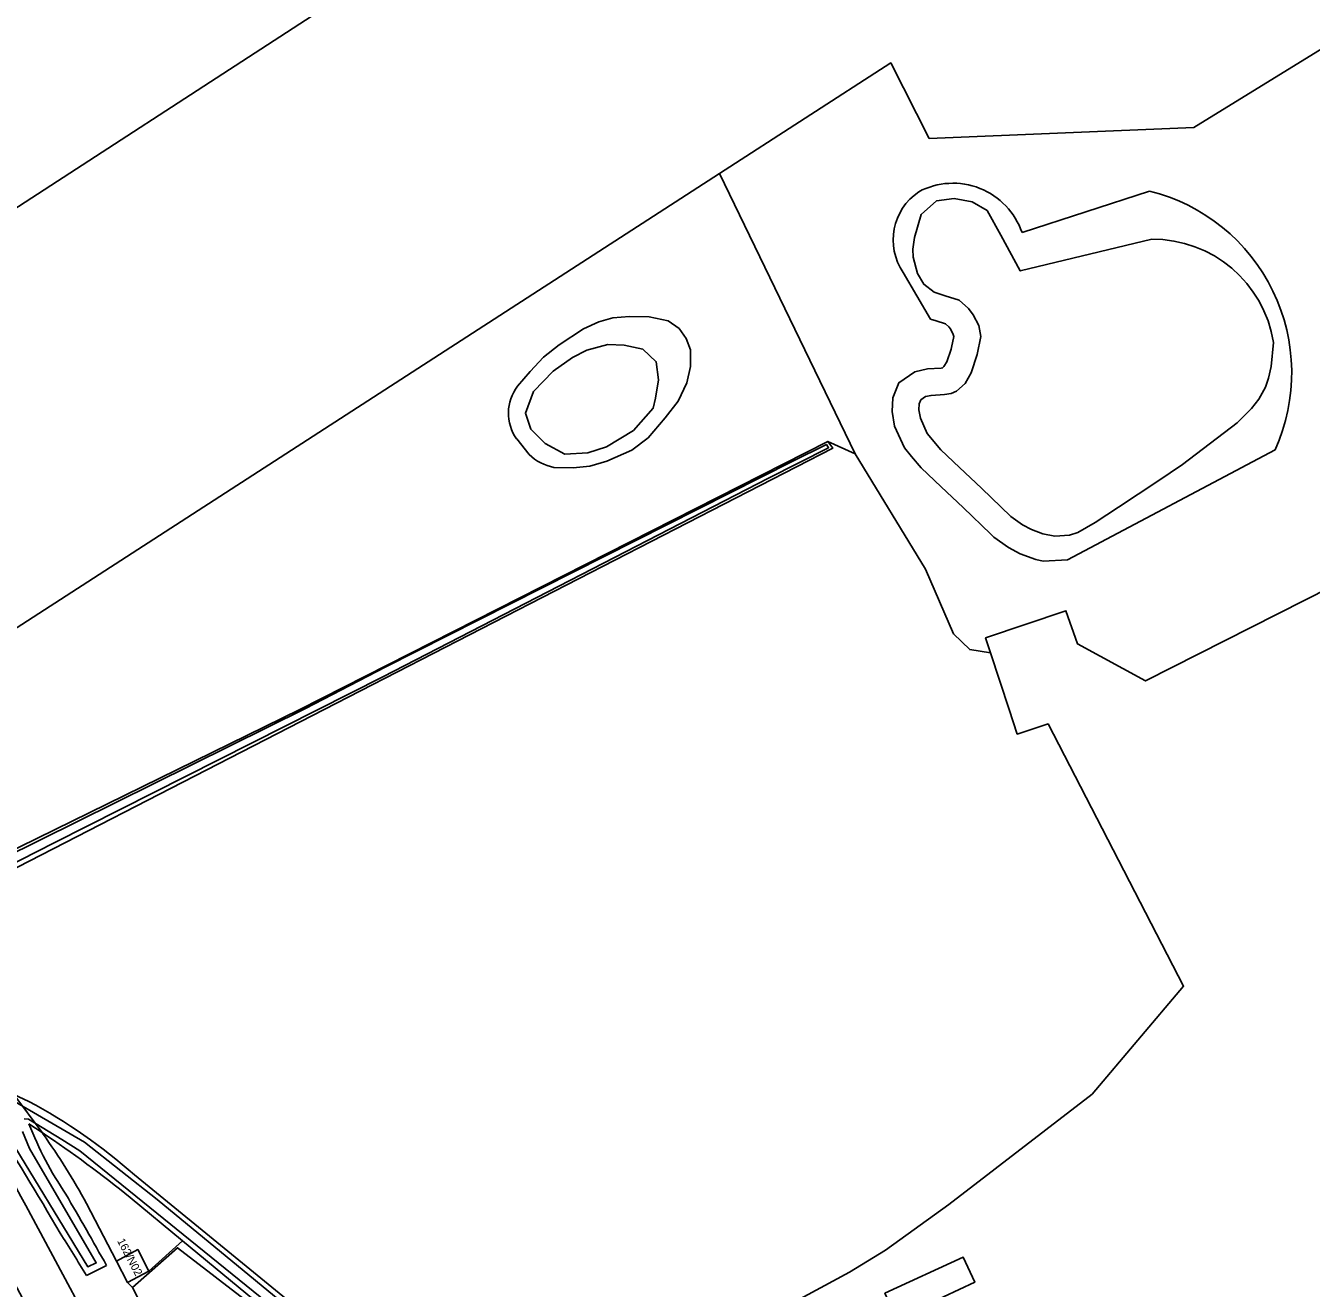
# Model space of a CAD drawing. Extents: x 156061 to 157804, y 383437 to 385640.
# Drawn here: x 157555.9 to 157716.6, y 383927.6 to 384085.5 of the extents above; entities that cross this region are included whole.
import ezdxf

# ---------------------------------------------------------------- set-up
doc = ezdxf.new("R2010")
doc.units = 0
for name, color, linetype in [('IMGEO_Bouwland', 7, 'Continuous'), ('IMGEO_Grasland_overig', 7, 'Continuous'), ('IMGEO_Groenvoorziening', 7, 'Continuous'), ('IMGEO_Hek', 7, 'Continuous'), ('IMGEO_Meer_plas_ven_vijver', 7, 'Continuous'), ('IMGEO_Oever', 7, 'Continuous'), ('IMGEO_Pand', 7, 'Continuous'), ('IMGEO_Pand_nummerreeks', 7, 'Continuous'), ('IMGEO_Rijbaan_lokaal_gesloten', 7, 'Continuous'), ('IMGEO_Waterloop', 7, 'Continuous')]:
    doc.layers.add(name, color=color, linetype=linetype)

msp = doc.modelspace()

# ---------------------------------------------------------------- linework, layer by layer
at = {"layer": 'IMGEO_Bouwland'}
for points in [[(157728.98, 384020.33), (157695.89, 384003.59), (157687.37, 384008.2), (157685.95, 384012.36), (157675.9, 384008.96), (157676.51, 384007.11), (157678.86, 384000), (157679.87, 383996.94), (157683.71, 383998.2), (157700.65, 383965.44), (157689.24, 383951.93), (157671.29, 383938.14), (157663.41, 383932.41), (157658.89, 383929.67), (157621.02, 383909.21)], [(157599.51, 383913.73), (157575.52, 383933.59), (157571.31, 383929.81), (157568.67, 383928.38), (157569.27, 383927.73), (157571.61, 383923.12)]]:
    msp.add_lwpolyline(points, dxfattribs=at)
msp.add_lwpolyline([(157674.54, 383928.41), (157664.75, 383923.85), (157663.32, 383927.02), (157673.08, 383931.55)], close=True, dxfattribs=at)
at = {"layer": 'IMGEO_Grasland_overig'}
for points in [[(157557.98, 383947.12), (157558.11, 383946.93)], [(157563.55, 383938.24), (157567.3, 383931.05), (157569.93, 383932.48), (157571.31, 383929.81), (157575.52, 383933.59), (157569, 383938.98)]]:
    msp.add_lwpolyline(points, dxfattribs=at)
for centre, radius, start, end in [((157477.63, 383826.71), 144.76, 50.8627, 56.2846), ((157490.52, 383898.58), 83.1, 28.5032, 35.5798)]:
    msp.add_arc(centre, radius, start, end, dxfattribs=at)
at = {"layer": 'IMGEO_Groenvoorziening'}
for points in [[(157375.38, 384222.59), (157376.59, 384220.76), (157342.51, 384199.14), (157412.58, 384119.43), (157466.22, 384058.41), (157468.2, 384056.16), (157486.53, 384035.35), (157490.12, 384031.28), (157495.9, 384024.71), (157497.66, 384025.67), (157500, 384027.19), (157642, 384119.41), (157643.26, 384117.4), (157752.8, 384188.65), (157752.54, 384194.33), (157751.65, 384205.4), (157750.08, 384220.37), (157749.32, 384226.2), (157748.06, 384232.65), (157745.14, 384247.49), (157743.64, 384254.59), (157738.42, 384274.55), (157728.47, 384313.42)], [(157642, 384119.41), (157500, 384027.19), (157497.66, 384025.67), (157500.2, 384022.65), (157517.01, 384002.7), (157519.18, 384000), (157525.95, 383991.61), (157642.66, 384067.03), (157664.05, 384080.85), (157668.86, 384071.41), (157701.95, 384072.77), (157719.58, 384083.63), (157721.28, 384082.41), (157730.2, 384064.28), (157731.75, 384064.23), (157756.47, 384074.37), (157756.55, 384074.87), (157757.36, 384079.82), (157760.48, 384099.13)], [(157719.58, 384083.63), (157701.95, 384072.77), (157668.86, 384071.41), (157664.05, 384080.85), (157642.66, 384067.03), (157659.62, 384031.98), (157668.41, 384017.54), (157671.91, 384009.46), (157673.93, 384007.49), (157676.51, 384007.11), (157675.9, 384008.96), (157685.95, 384012.36), (157687.37, 384008.2), (157695.89, 384003.59), (157728.98, 384020.33)], [(157680.46, 384059.63), (157696.4, 384064.82)], [(157712.09, 384032.48), (157686.12, 384018.7), (157683.1, 384018.57), (157682.17, 384018.74), (157680.24, 384019.47), (157678.75, 384020.26), (157676.93, 384021.56), (157676.57, 384021.91), (157673.1, 384025.27), (157670.36, 384027.84), (157667.86, 384030.21), (157666.65, 384031.65), (157665.75, 384032.73), (157664.51, 384035.42), (157664.23, 384037.27), (157664.31, 384038.96), (157665.08, 384040.86), (157667.04, 384042.24), (157668.64, 384042.58), (157670.37, 384042.69), (157670.53, 384042.72), (157670.7, 384042.87), (157671.04, 384043.48), (157671.58, 384045.05), (157671.64, 384045.25), (157671.92, 384046.64), (157671.87, 384046.88), (157671.51, 384047.58), (157671.3, 384047.86), (157670.89, 384048.22), (157669.73, 384048.59), (157669.02, 384048.81), (157665.6, 384054.64)], [(157617.42, 384040.42), (157618.97, 384042.27), (157620.64, 384044.06), (157622.61, 384045.61), (157625.66, 384047.59), (157627.57, 384048.48), (157629.3, 384048.96), (157631.39, 384049.14), (157633.84, 384049.08), (157636.22, 384048.6), (157637.6, 384047.65), (157638.49, 384046.39), (157639.03, 384044.96), (157639.03, 384042.87), (157638.55, 384040.84), (157637.48, 384038.57), (157635.87, 384036.47), (157633.72, 384033.97), (157631.69, 384032.41), (157628.58, 384031.04), (157626.43, 384030.44), (157624.34, 384030.2), (157621.96, 384030.26)], [(157683.71, 383998.2), (157679.87, 383996.94), (157678.86, 384000), (157676.51, 384007.11), (157673.93, 384007.49), (157671.91, 384009.46), (157668.41, 384017.54), (157659.62, 384031.98), (157656.19, 384033.53), (157656.8, 384032.66), (157593.24, 384000), (157541.68, 383973.51), (157539.29, 383972.68), (157538.96, 383972.37), (157554.47, 383951.89), (157556.32, 383951.02)], [(157618.85, 384031.87), (157617.3, 384033.85)], [(157569.52, 383941.83), (157610.5, 383908.34), (157608.98, 383906.43), (157610.74, 383905.07), (157621.02, 383909.21), (157658.89, 383929.67), (157663.41, 383932.41), (157671.29, 383938.14), (157689.24, 383951.93), (157700.65, 383965.44), (157683.71, 383998.2)], [(157558.11, 383946.93), (157557.98, 383947.12), (157556.34, 383948.2)], [(157555.94, 383937.98), (157567.65, 383916.15), (157574.44, 383902.8), (157575.84, 383901.42), (157579.95, 383892.19), (157580.13, 383890.35), (157580.2, 383889.6), (157583.74, 383880.91), (157594.17, 383855.64), (157601.93, 383836.64), (157610.74, 383815.24), (157612.75, 383810.25)], [(157569.27, 383927.73), (157568.67, 383928.38), (157567.3, 383931.05), (157563.55, 383938.24)], [(157566.04, 383930.51), (157563.52, 383929.25)], [(157709.13, 383838.3), (157708.9, 383838.83), (157708.52, 383839.48), (157702.8, 383849.36), (157707.55, 383840.38), (157700.2, 383834.34), (157695.92, 383830.81), (157693.54, 383829.05), (157691.04, 383827.5), (157689.84, 383826.75), (157683.07, 383823.26), (157676.59, 383820.43), (157634.61, 383803.39), (157626.26, 383803.73), (157620.27, 383810.26), (157611.86, 383828.59), (157592.66, 383877.06), (157588.09, 383888.13), (157579.36, 383907.86), (157571.61, 383923.12), (157569.27, 383927.73)]]:
    msp.add_lwpolyline(points, dxfattribs=at)
msp.add_lwpolyline([(157656.19, 384033.53), (157659.62, 384031.98), (157642.66, 384067.03), (157525.95, 383991.61), (157532.83, 383983.08), (157542.78, 383987.84), (157543.11, 383987.19), (157544.65, 383984.1), (157548.18, 383985.84), (157549.57, 383983.08), (157545.89, 383981.26), (157537.64, 383977.09), (157537.39, 383975.02), (157549.75, 383980.34), (157553.01, 383981.76), (157590.21, 384000)], close=True, dxfattribs=at)
for centre, radius, start, end in [((157671.63, 384058.71), 7.27, 124.1098, 214.0202), ((157671.82, 384056.67), 9.13, 18.9073, 117.9158), ((157690.73, 384042.09), 23.43, 335.7803, 75.9968), ((157621.81, 384037.05), 5.54, 142.5536, 215.3713), ((157623.27, 384036.58), 6.45, 226.8172, 258.2653), ((157379.41, 383843.74), 200.11, 28.0956, 40.0394), ((157206.53, 383728.93), 409.14, 30.1696, 34.9235), ((157524.04, 383890.59), 68.51, 48.407, 61.8863), ((157597.91, 383964.44), 44.63, 201.3477, 214.1031), ((157490.52, 383898.58), 83.1, 28.5032, 35.5798), ((157158.63, 383703.58), 466.34, 29.118, 30.3786), ((157329.09, 383788.72), 273.32, 30.94, 32.2461)]:
    msp.add_arc(centre, radius, start, end, dxfattribs=at)
at = {"layer": 'IMGEO_Hek'}
for points in [[(157500, 384027.19), (157642, 384119.41)], [(157683.71, 383998.2), (157700.65, 383965.44)], [(157608.98, 383906.43), (157610.74, 383905.07), (157621.02, 383909.21), (157658.89, 383929.67), (157663.41, 383932.41), (157671.29, 383938.14), (157689.24, 383951.93), (157700.65, 383965.44)], [(157554.47, 383951.89), (157557.98, 383947.12)], [(157557.98, 383947.12), (157558.11, 383946.93)], [(157567.3, 383931.05), (157563.55, 383938.24)], [(157569.27, 383927.73), (157574.89, 383932.72), (157599.51, 383913.73)], [(157569.27, 383927.73), (157568.67, 383928.38)]]:
    msp.add_lwpolyline(points, dxfattribs=at)
msp.add_arc((157490.52, 383898.58), 83.1, 28.5032, 35.5798, dxfattribs=at)
at = {"layer": 'IMGEO_Meer_plas_ven_vijver'}
msp.add_lwpolyline([(157696.66, 384058.8), (157680.24, 384054.83), (157677.82, 384059.29), (157676.08, 384062.39), (157674.21, 384063.49), (157671.96, 384063.88), (157669.75, 384063.58), (157667.84, 384061.88), (157667, 384059.03), (157666.82, 384057.55), (157666.86, 384056.57), (157667.4, 384054.51), (157668.2, 384053.18), (157669.47, 384052.16), (157670.73, 384051.76), (157670.85, 384051.73), (157672.58, 384051.18), (157673.76, 384050.12), (157674.33, 384049.36), (157675.04, 384048.01), (157675.32, 384046.65), (157674.87, 384044.38), (157674.09, 384042.11), (157673.34, 384040.76), (157672.26, 384039.79), (157671.6, 384039.52), (157670.76, 384039.38), (157669.1, 384039.27), (157668.39, 384039.12), (157667.8, 384038.7), (157667.61, 384038.23), (157667.57, 384037.48), (157667.76, 384036.42), (157668.6, 384034.51), (157670.29, 384032.49), (157672.64, 384030.27), (157675.4, 384027.67), (157679.06, 384024.13), (157680.51, 384023.1), (157681.62, 384022.51), (157683.07, 384021.96), (157684.56, 384021.68), (157686.39, 384021.79), (157687.42, 384022.14), (157689.58, 384023.39), (157692.52, 384025.3), (157697.45, 384028.56), (157700.5, 384030.63), (157707.36, 384035.86), (157709.12, 384037.64), (157710.04, 384038.81), (157710.88, 384040.31), (157711.28, 384041.43), (157711.59, 384042.87), (157711.88, 384045.88)], dxfattribs=at)
msp.add_lwpolyline([(157624.28, 384044.03), (157621.85, 384042.3), (157619.38, 384039.75), (157618.39, 384037.06), (157619.05, 384035.07), (157620.85, 384033.27), (157623.32, 384031.94), (157626.2, 384032.09), (157628.52, 384032.83), (157631.91, 384034.89), (157634.34, 384037.69), (157634.64, 384038.91), (157635.04, 384041.23), (157634.75, 384043.48), (157633.05, 384045.06), (157630.73, 384045.54), (157628.67, 384045.65), (157626.05, 384044.95)], close=True, dxfattribs=at)
msp.add_arc((157696.77, 384043.5), 15.3, 8.9152, 90.4113, dxfattribs=at)
at = {"layer": 'IMGEO_Oever'}
for points in [[(157696.4, 384064.82), (157680.46, 384059.63)], [(157667.84, 384061.88), (157669.75, 384063.58), (157671.96, 384063.88), (157674.21, 384063.49), (157676.08, 384062.39), (157677.82, 384059.29), (157680.24, 384054.83), (157696.66, 384058.8)], [(157711.88, 384045.88), (157711.59, 384042.87), (157711.28, 384041.43), (157710.88, 384040.31), (157710.04, 384038.81), (157709.12, 384037.64), (157707.36, 384035.86), (157700.5, 384030.63), (157697.45, 384028.56), (157692.52, 384025.3), (157689.58, 384023.39), (157687.42, 384022.14), (157686.39, 384021.79), (157684.56, 384021.68), (157683.07, 384021.96), (157681.62, 384022.51), (157680.51, 384023.1), (157679.06, 384024.13), (157675.4, 384027.67), (157672.64, 384030.27), (157670.29, 384032.49), (157668.6, 384034.51), (157667.76, 384036.42), (157667.57, 384037.48), (157667.61, 384038.23), (157667.8, 384038.7), (157668.39, 384039.12), (157669.1, 384039.27), (157670.76, 384039.38), (157671.6, 384039.52), (157672.26, 384039.79), (157673.34, 384040.76), (157674.09, 384042.11), (157674.87, 384044.38), (157675.32, 384046.65), (157675.04, 384048.01), (157674.33, 384049.36), (157673.76, 384050.12), (157672.58, 384051.18), (157670.85, 384051.73), (157670.73, 384051.76), (157669.47, 384052.16), (157668.2, 384053.18), (157667.4, 384054.51), (157666.86, 384056.57), (157666.82, 384057.55), (157667, 384059.03), (157667.84, 384061.88)], [(157665.6, 384054.64), (157669.02, 384048.81), (157669.73, 384048.59), (157670.89, 384048.22), (157671.3, 384047.86), (157671.51, 384047.58), (157671.87, 384046.88), (157671.92, 384046.64), (157671.64, 384045.25), (157671.58, 384045.05), (157671.04, 384043.48), (157670.7, 384042.87), (157670.53, 384042.72), (157670.37, 384042.69), (157668.64, 384042.58), (157667.04, 384042.24), (157665.08, 384040.86), (157664.31, 384038.96), (157664.23, 384037.27), (157664.51, 384035.42), (157665.75, 384032.73), (157666.65, 384031.65), (157667.86, 384030.21), (157670.36, 384027.84), (157673.1, 384025.27), (157676.57, 384021.91), (157676.93, 384021.56), (157678.75, 384020.26), (157680.24, 384019.47), (157682.17, 384018.74), (157683.1, 384018.57), (157686.12, 384018.7), (157712.09, 384032.48)], [(157637.6, 384047.65), (157636.22, 384048.6), (157633.84, 384049.08), (157631.39, 384049.14), (157629.3, 384048.96), (157627.57, 384048.48), (157625.66, 384047.59), (157622.61, 384045.61), (157620.64, 384044.06), (157618.97, 384042.27), (157617.42, 384040.42)], [(157621.96, 384030.26), (157624.34, 384030.2), (157626.43, 384030.44), (157628.58, 384031.04), (157631.69, 384032.41), (157633.72, 384033.97), (157635.87, 384036.47), (157637.48, 384038.57), (157638.55, 384040.84), (157639.03, 384042.87), (157639.03, 384044.96), (157638.49, 384046.39), (157637.6, 384047.65)], [(157538.96, 383972.37), (157539.29, 383972.68), (157541.68, 383973.51), (157593.24, 384000), (157656.8, 384032.66), (157656.19, 384033.53), (157590.21, 384000), (157553.01, 383981.76), (157549.75, 383980.34), (157537.39, 383975.02), (157536.33, 383974.56), (157534.2, 383977.23), (157532.58, 383976.37), (157538.56, 383967.99), (157542, 383963.16)], [(157553, 383981.32), (157590.9, 384000.13), (157600.87, 384005.3), (157651.72, 384031), (157656.01, 384033.12), (157656.27, 384032.74), (157648.75, 384028.94), (157600.55, 384004.1), (157559.58, 383983.38), (157544.42, 383975.69)], [(157617.3, 384033.85), (157618.85, 384031.87)], [(157553.33, 383951.7), (157563.27, 383945.93), (157572.36, 383938.75), (157609.22, 383908.39), (157608.66, 383907.63), (157562.7, 383944.84), (157560.43, 383946.26), (157556.27, 383948.79), (157555.76, 383948.82)], [(157556.32, 383951.02), (157554.47, 383951.89)], [(157556.34, 383948.2), (157557.98, 383947.12)], [(157555.54, 383947.24), (157556.41, 383945.12), (157564.76, 383930.83), (157563.7, 383930.34), (157553.42, 383947.27)], [(157569, 383938.98), (157575.52, 383933.59), (157599.51, 383913.73), (157608.72, 383906.11), (157608.98, 383906.43), (157610.5, 383908.34), (157569.52, 383941.83)], [(157563.52, 383929.25), (157566.04, 383930.51)]]:
    msp.add_lwpolyline(points, dxfattribs=at)
msp.add_lwpolyline([(157624.28, 384044.03), (157626.05, 384044.95), (157628.67, 384045.65), (157630.73, 384045.54), (157633.05, 384045.06), (157634.75, 384043.48), (157635.04, 384041.23), (157634.64, 384038.91), (157634.34, 384037.69), (157631.91, 384034.89), (157628.52, 384032.83), (157626.2, 384032.09), (157623.32, 384031.94), (157620.85, 384033.27), (157619.05, 384035.07), (157618.39, 384037.06), (157619.38, 384039.75), (157621.85, 384042.3)], close=True, dxfattribs=at)
for centre, radius, start, end in [((157671.63, 384058.71), 7.27, 124.1098, 214.0202), ((157671.82, 384056.67), 9.13, 18.9073, 117.9158), ((157690.73, 384042.09), 23.43, 335.7803, 75.9968), ((157696.77, 384043.5), 15.3, 8.9152, 90.4113), ((157621.81, 384037.05), 5.54, 142.5536, 215.3713), ((157623.27, 384036.58), 6.45, 226.8172, 258.2653), ((157206.53, 383728.93), 409.14, 30.1696, 34.9235), ((157524.04, 383890.59), 68.51, 48.407, 61.8863), ((157597.91, 383964.44), 44.63, 201.3477, 214.1031), ((157477.63, 383826.71), 144.76, 50.8627, 56.2846), ((157158.63, 383703.58), 466.34, 29.118, 30.3786), ((157329.09, 383788.72), 273.32, 30.94, 32.2461)]:
    msp.add_arc(centre, radius, start, end, dxfattribs=at)
at = {"layer": 'IMGEO_Pand'}
for points in [[(157567.3, 383931.05), (157568.67, 383928.38), (157571.31, 383929.81), (157569.93, 383932.48)], [(157664.75, 383923.85), (157674.54, 383928.41), (157673.08, 383931.55), (157663.32, 383927.02)]]:
    msp.add_lwpolyline(points, close=True, dxfattribs=at)
at = {"layer": 'IMGEO_Rijbaan_lokaal_gesloten'}
msp.add_lwpolyline([(157552.88, 383931.4), (157563.85, 383910.77), (157565.81, 383907.11), (157568.7, 383900.75), (157570.14, 383897.53), (157571.05, 383897.92), (157571.17, 383897.97), (157574.78, 383899.59), (157575.65, 383899.99), (157574.44, 383902.8), (157567.65, 383916.15), (157555.94, 383937.98)], dxfattribs=at)
msp.add_arc((157379.41, 383843.74), 200.11, 28.0956, 40.0394, dxfattribs=at)
at = {"layer": 'IMGEO_Waterloop'}
for points in [[(157544.42, 383975.69), (157559.58, 383983.38), (157600.55, 384004.1), (157648.75, 384028.94), (157656.27, 384032.74), (157656.01, 384033.12), (157651.72, 384031), (157600.87, 384005.3), (157590.9, 384000.13), (157553, 383981.32)], [(157555.76, 383948.82), (157556.27, 383948.79), (157560.43, 383946.26), (157562.7, 383944.84), (157608.66, 383907.63), (157609.22, 383908.39), (157572.36, 383938.75), (157563.27, 383945.93), (157553.33, 383951.7)], [(157553.42, 383947.27), (157563.7, 383930.34), (157564.76, 383930.83), (157556.41, 383945.12), (157555.54, 383947.24)]]:
    msp.add_lwpolyline(points, dxfattribs=at)

# ---------------------------------------------------------------- texts
at = {"layer": 'IMGEO_Pand_nummerreeks'}
msp.add_text('162/N02', height=1, rotation=297.699, dxfattribs=at).set_placement((157567.34, 383933.57))

doc.saveas('drawing.dxf')
